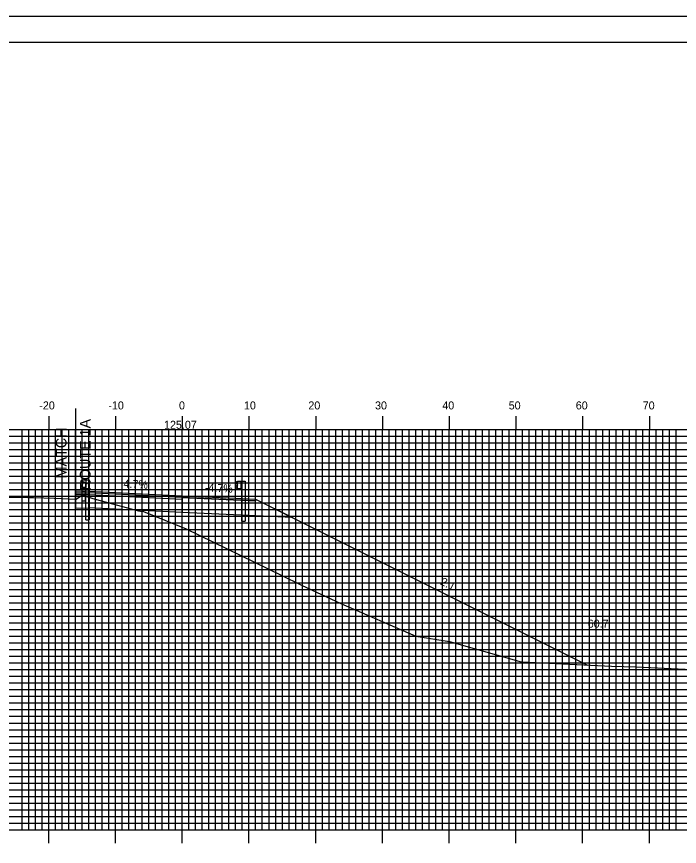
# Model space of a CAD drawing. Extents: x 857265 to 857608, y 364366 to 364586.
# Drawn here: x 857405.5 to 857504.8, y 364461.3 to 364585.7 of the extents above; entities that cross this region are included whole.
import ezdxf

# ---------------------------------------------------------------- set-up
doc = ezdxf.new("R2010")
doc.units = 0
for name, color, linetype in [('ANNOTATION', 7, 'Continuous'), ('BORDER', 7, 'Continuous'), ('D_Guardrail_Beam_Rt', 7, 'Continuous'), ('D_Roadway_Centerline_Text', 7, 'Continuous'), ('D_Roadway_Edge_Shoulder', 7, 'Continuous'), ('D_Roadway_Edge_TW', 7, 'Continuous'), ('D_Roadway_Pavement', 7, 'Continuous'), ('D_Roadway_SlopeLines', 7, 'Continuous'), ('D_Roadway_SubGrade', 7, 'Continuous'), ('D_Text_Standard', 7, 'Continuous'), ('H_V ANNOTATION', 7, 'Continuous'), ('MAJOR', 7, 'Continuous'), ('MINOR', 7, 'Continuous'), ('PLOT BOUNDARY', 7, 'Continuous'), ('S_Curb_Type_1', 7, 'Continuous'), ('S_Guardrail_Beam', 7, 'Continuous'), ('S_Roadway_Centerline', 7, 'Continuous')]:
    doc.layers.add(name, color=color, linetype=linetype)

msp = doc.modelspace()

# ---------------------------------------------------------------- linework, layer by layer
at = {"layer": 'BORDER'}
msp.add_lwpolyline([(857280.74, 364371.79), (857600.74, 364371.79), (857600.74, 364581.79), (857280.74, 364581.79)], close=True, dxfattribs=at)
at = {"layer": 'D_Guardrail_Beam_Rt'}
for p, q in [((857438.52, 364515.96), (857438.37, 364515.86)), ((857438.37, 364515.71), (857438.57, 364515.58)), ((857438.57, 364515.38), (857438.37, 364515.24)), ((857438.37, 364515.1), (857438.52, 364515)), ((857438.61, 364515.98), (857438.53, 364515.96)), ((857438.6, 364515.51), (857438.6, 364515.44)), ((857438.61, 364516.06), (857439.29, 364516.06)), ((857438.61, 364514.9), (857438.61, 364516.06)), ((857439.13, 364516.06), (857439.13, 364514.9)), ((857439.23, 364516.06), (857439.23, 364514.9)), ((857439.29, 364516.06), (857439.76, 364516.06)), ((857439.29, 364516.06), (857439.29, 364514.9)), ((857439.76, 364516.06), (857439.76, 364510.06)), ((857438.53, 364514.99), (857438.61, 364514.98)), ((857439.29, 364514.9), (857438.61, 364514.9)), ((857439.27, 364510.06), (857439.27, 364514.9)), ((857439.27, 364510.06), (857439.76, 364510.06))]:
    msp.add_line(p, q, dxfattribs=at)
for centre, major_axis, start_param, end_param in [((857438.42, 364515.79), (-0.0877, 0), 5.323254, 7.243116), ((857438.42, 364515.17), (-0.0877, 0), 5.323254, 7.243116), ((857438.54, 364515.92), (-0.0417, 0), 4.907132, 5.323254), ((857438.52, 364515.51), (0.0789, 0), 0, 0.959931), ((857438.52, 364515.44), (0.0789, 0), 5.323254, 6.283185), ((857438.54, 364515.03), (-0.0417, 0), 0.959931, 1.376053)]:
    msp.add_ellipse(centre, major_axis=major_axis, ratio=0.995501, start_param=start_param, end_param=end_param, dxfattribs=at)
at = {"layer": 'D_Roadway_Edge_Shoulder'}
msp.add_lwpolyline([(857414.34, 364514.23), (857416.34, 364514.27), (857416.34, 364514.52), (857414.34, 364514.48)], dxfattribs=at)
msp.add_lwpolyline([(857430.34, 364513.86), (857438.34, 364513.48), (857438.34, 364513.48), (857441.34, 364513.34), (857441.34, 364513.09), (857430.34, 364513.61)], close=True, dxfattribs=at)
at = {"layer": 'D_Roadway_Edge_TW'}
msp.add_lwpolyline([(857416.34, 364514.52), (857430.34, 364513.86), (857430.34, 364513.61), (857416.34, 364514.27)], close=True, dxfattribs=at)
at = {"layer": 'D_Roadway_Pavement'}
for points in [[(857414.34, 364513.98), (857416.34, 364514.02), (857416.34, 364514.27), (857414.34, 364514.23)], [(857430.34, 364513.61), (857430.34, 364513.36)], [(857430.34, 364513.61), (857430.34, 364513.36)], [(857430.34, 364513.61), (857430.34, 364513.36)], [(857430.34, 364513.61), (857430.34, 364513.36)]]:
    msp.add_lwpolyline(points, dxfattribs=at)
at = {"layer": 'D_Roadway_SlopeLines'}
msp.add_line((857441.34, 364513.34), (857491.08, 364488.48), dxfattribs=at)
at = {"layer": 'D_Roadway_SubGrade'}
msp.add_line((857414.34, 364526.92), (857414.34, 364511.96), dxfattribs=at)
msp.add_lwpolyline([(857414.34, 364511.98), (857416.34, 364512.02), (857416.34, 364514.02), (857414.34, 364513.98)], dxfattribs=at)
for points in [[(857416.34, 364514.02), (857430.34, 364513.36), (857430.34, 364511.36), (857416.34, 364512.02)], [(857430.34, 364513.36), (857430.34, 364513.61), (857441.34, 364513.09), (857441.34, 364513.34), (857446.86, 364510.57), (857430.34, 364511.36)]]:
    msp.add_lwpolyline(points, close=True, dxfattribs=at)
at = {"layer": 'MAJOR'}
for p, q in [((857410.34, 364525.79), (857410.34, 364523.79)), ((857420.34, 364525.79), (857420.34, 364523.79)), ((857430.34, 364525.79), (857430.34, 364523.79)), ((857440.34, 364525.79), (857440.34, 364523.79)), ((857450.34, 364525.79), (857450.34, 364523.79)), ((857460.34, 364525.79), (857460.34, 364523.79)), ((857470.34, 364525.79), (857470.34, 364523.79)), ((857480.34, 364525.79), (857480.34, 364523.79)), ((857490.34, 364525.79), (857490.34, 364523.79)), ((857500.34, 364525.79), (857500.34, 364523.79)), ((857290.34, 364523.79), (857570.34, 364523.79)), ((857290.34, 364523.79), (857570.34, 364523.79)), ((857410.34, 364463.79), (857410.34, 364523.79)), ((857420.34, 364463.79), (857420.34, 364523.79)), ((857430.34, 364463.79), (857430.34, 364523.79)), ((857440.34, 364463.79), (857440.34, 364523.79)), ((857450.34, 364463.79), (857450.34, 364523.79)), ((857460.34, 364463.79), (857460.34, 364523.79)), ((857470.34, 364463.79), (857470.34, 364523.79)), ((857480.34, 364463.79), (857480.34, 364523.79)), ((857490.34, 364463.79), (857490.34, 364523.79)), ((857500.34, 364463.79), (857500.34, 364523.79)), ((857290.34, 364518.79), (857570.34, 364518.79)), ((857290.34, 364513.79), (857570.34, 364513.79)), ((857290.34, 364508.79), (857570.34, 364508.79)), ((857290.34, 364503.79), (857570.34, 364503.79)), ((857290.34, 364498.79), (857570.34, 364498.79)), ((857290.34, 364493.79), (857570.34, 364493.79)), ((857290.34, 364488.79), (857570.34, 364488.79)), ((857290.34, 364483.79), (857570.34, 364483.79)), ((857290.34, 364478.79), (857570.34, 364478.79)), ((857290.34, 364473.79), (857570.34, 364473.79)), ((857290.34, 364468.79), (857570.34, 364468.79)), ((857290.34, 364463.79), (857570.34, 364463.79)), ((857290.34, 364463.79), (857570.34, 364463.79)), ((857410.34, 364461.78), (857410.34, 364463.79)), ((857420.34, 364461.78), (857420.34, 364463.79)), ((857430.34, 364461.78), (857430.34, 364463.79)), ((857440.34, 364461.78), (857440.34, 364463.79)), ((857450.34, 364461.78), (857450.34, 364463.79)), ((857460.34, 364461.78), (857460.34, 364463.79)), ((857470.34, 364461.78), (857470.34, 364463.79)), ((857480.34, 364461.78), (857480.34, 364463.79)), ((857490.34, 364461.78), (857490.34, 364463.79)), ((857500.34, 364461.78), (857500.34, 364463.79))]:
    msp.add_line(p, q, dxfattribs=at)
at = {"layer": 'MINOR'}
for p, q in [((857290.34, 364522.79), (857570.34, 364522.79)), ((857406.34, 364463.79), (857406.34, 364523.79)), ((857407.34, 364463.79), (857407.34, 364523.79)), ((857408.34, 364463.79), (857408.34, 364523.79)), ((857409.34, 364463.79), (857409.34, 364523.79)), ((857411.34, 364463.79), (857411.34, 364523.79)), ((857412.34, 364463.79), (857412.34, 364523.79)), ((857413.34, 364463.79), (857413.34, 364523.79)), ((857414.34, 364463.79), (857414.34, 364523.79)), ((857415.34, 364463.79), (857415.34, 364523.79)), ((857416.34, 364463.79), (857416.34, 364523.79)), ((857417.34, 364463.79), (857417.34, 364523.79)), ((857418.34, 364463.79), (857418.34, 364523.79)), ((857419.34, 364463.79), (857419.34, 364523.79)), ((857421.34, 364463.79), (857421.34, 364523.79)), ((857422.34, 364463.79), (857422.34, 364523.79)), ((857423.34, 364463.79), (857423.34, 364523.79)), ((857424.34, 364463.79), (857424.34, 364523.79)), ((857425.34, 364463.79), (857425.34, 364523.79)), ((857426.34, 364463.79), (857426.34, 364523.79)), ((857427.34, 364463.79), (857427.34, 364523.79)), ((857428.34, 364463.79), (857428.34, 364523.79)), ((857429.34, 364463.79), (857429.34, 364523.79)), ((857431.34, 364463.79), (857431.34, 364523.79)), ((857432.34, 364463.79), (857432.34, 364523.79)), ((857433.34, 364463.79), (857433.34, 364523.79)), ((857434.34, 364463.79), (857434.34, 364523.79)), ((857435.34, 364463.79), (857435.34, 364523.79)), ((857436.34, 364463.79), (857436.34, 364523.79)), ((857437.34, 364463.79), (857437.34, 364523.79)), ((857438.34, 364463.79), (857438.34, 364523.79)), ((857439.34, 364463.79), (857439.34, 364523.79)), ((857441.34, 364463.79), (857441.34, 364523.79)), ((857442.34, 364463.79), (857442.34, 364523.79)), ((857443.34, 364463.79), (857443.34, 364523.79)), ((857444.34, 364463.79), (857444.34, 364523.79)), ((857445.34, 364463.79), (857445.34, 364523.79)), ((857446.34, 364463.79), (857446.34, 364523.79)), ((857447.34, 364463.79), (857447.34, 364523.79)), ((857448.34, 364463.79), (857448.34, 364523.79)), ((857449.34, 364463.79), (857449.34, 364523.79)), ((857451.34, 364463.79), (857451.34, 364523.79)), ((857452.34, 364463.79), (857452.34, 364523.79)), ((857453.34, 364463.79), (857453.34, 364523.79)), ((857454.34, 364463.79), (857454.34, 364523.79)), ((857455.34, 364463.79), (857455.34, 364523.79)), ((857456.34, 364463.79), (857456.34, 364523.79)), ((857457.34, 364463.79), (857457.34, 364523.79)), ((857458.34, 364463.79), (857458.34, 364523.79)), ((857459.34, 364463.79), (857459.34, 364523.79)), ((857461.34, 364463.79), (857461.34, 364523.79)), ((857462.34, 364463.79), (857462.34, 364523.79)), ((857463.34, 364463.79), (857463.34, 364523.79)), ((857464.34, 364463.79), (857464.34, 364523.79)), ((857465.34, 364463.79), (857465.34, 364523.79)), ((857466.34, 364463.79), (857466.34, 364523.79)), ((857467.34, 364463.79), (857467.34, 364523.79)), ((857468.34, 364463.79), (857468.34, 364523.79)), ((857469.34, 364463.79), (857469.34, 364523.79)), ((857471.34, 364463.79), (857471.34, 364523.79)), ((857472.34, 364463.79), (857472.34, 364523.79)), ((857473.34, 364463.79), (857473.34, 364523.79)), ((857474.34, 364463.79), (857474.34, 364523.79)), ((857475.34, 364463.79), (857475.34, 364523.79)), ((857476.34, 364463.79), (857476.34, 364523.79)), ((857477.34, 364463.79), (857477.34, 364523.79)), ((857478.34, 364463.79), (857478.34, 364523.79)), ((857479.34, 364463.79), (857479.34, 364523.79)), ((857481.34, 364463.79), (857481.34, 364523.79)), ((857482.34, 364463.79), (857482.34, 364523.79)), ((857483.34, 364463.79), (857483.34, 364523.79)), ((857484.34, 364463.79), (857484.34, 364523.79)), ((857485.34, 364463.79), (857485.34, 364523.79)), ((857486.34, 364463.79), (857486.34, 364523.79)), ((857487.34, 364463.79), (857487.34, 364523.79)), ((857488.34, 364463.79), (857488.34, 364523.79)), ((857489.34, 364463.79), (857489.34, 364523.79)), ((857491.34, 364463.79), (857491.34, 364523.79)), ((857492.34, 364463.79), (857492.34, 364523.79)), ((857493.34, 364463.79), (857493.34, 364523.79)), ((857494.34, 364463.79), (857494.34, 364523.79)), ((857495.34, 364463.79), (857495.34, 364523.79)), ((857496.34, 364463.79), (857496.34, 364523.79)), ((857497.34, 364463.79), (857497.34, 364523.79)), ((857498.34, 364463.79), (857498.34, 364523.79)), ((857499.34, 364463.79), (857499.34, 364523.79)), ((857501.34, 364463.79), (857501.34, 364523.79)), ((857502.34, 364463.79), (857502.34, 364523.79)), ((857503.34, 364463.79), (857503.34, 364523.79)), ((857504.34, 364463.79), (857504.34, 364523.79)), ((857290.34, 364521.79), (857570.34, 364521.79)), ((857290.34, 364520.79), (857570.34, 364520.79)), ((857290.34, 364519.79), (857570.34, 364519.79)), ((857290.34, 364517.79), (857570.34, 364517.79)), ((857290.34, 364516.79), (857570.34, 364516.79)), ((857290.34, 364515.79), (857570.34, 364515.79)), ((857290.34, 364514.79), (857570.34, 364514.79)), ((857290.34, 364512.79), (857570.34, 364512.79)), ((857290.34, 364511.79), (857570.34, 364511.79)), ((857290.34, 364510.79), (857570.34, 364510.79)), ((857290.34, 364509.79), (857570.34, 364509.79)), ((857290.34, 364507.79), (857570.34, 364507.79)), ((857290.34, 364506.79), (857570.34, 364506.79)), ((857290.34, 364505.79), (857570.34, 364505.79)), ((857290.34, 364504.79), (857570.34, 364504.79)), ((857290.34, 364502.79), (857570.34, 364502.79)), ((857290.34, 364501.79), (857570.34, 364501.79)), ((857290.34, 364500.79), (857570.34, 364500.79)), ((857290.34, 364499.79), (857570.34, 364499.79)), ((857290.34, 364497.79), (857570.34, 364497.79)), ((857290.34, 364496.79), (857570.34, 364496.79)), ((857290.34, 364495.79), (857570.34, 364495.79)), ((857290.34, 364494.79), (857570.34, 364494.79)), ((857290.34, 364492.79), (857570.34, 364492.79)), ((857290.34, 364491.79), (857570.34, 364491.79)), ((857290.34, 364490.79), (857570.34, 364490.79)), ((857290.34, 364489.79), (857570.34, 364489.79)), ((857290.34, 364487.79), (857570.34, 364487.79)), ((857290.34, 364486.79), (857570.34, 364486.79)), ((857290.34, 364485.79), (857570.34, 364485.79)), ((857290.34, 364484.79), (857570.34, 364484.79)), ((857290.34, 364482.79), (857570.34, 364482.79)), ((857290.34, 364481.79), (857570.34, 364481.79)), ((857290.34, 364480.79), (857570.34, 364480.79)), ((857290.34, 364479.79), (857570.34, 364479.79)), ((857290.34, 364477.79), (857570.34, 364477.79)), ((857290.34, 364476.79), (857570.34, 364476.79)), ((857290.34, 364475.79), (857570.34, 364475.79)), ((857290.34, 364474.79), (857570.34, 364474.79)), ((857290.34, 364472.79), (857570.34, 364472.79)), ((857290.34, 364471.79), (857570.34, 364471.79)), ((857290.34, 364470.79), (857570.34, 364470.79)), ((857290.34, 364469.79), (857570.34, 364469.79)), ((857290.34, 364467.79), (857570.34, 364467.79)), ((857290.34, 364466.79), (857570.34, 364466.79)), ((857290.34, 364465.79), (857570.34, 364465.79)), ((857290.34, 364464.79), (857570.34, 364464.79))]:
    msp.add_line(p, q, dxfattribs=at)
at = {"layer": 'PLOT BOUNDARY'}
msp.add_lwpolyline([(857264.55, 364365.67), (857604.55, 364365.67), (857604.55, 364585.67), (857264.55, 364585.67)], close=True, dxfattribs=at)
at = {"layer": 'S_Curb_Type_1'}
msp.add_lwpolyline([(857415.35, 364514.53), (857415.77, 364514.53), (857415.77, 364513.03), (857415.35, 364513.03)], close=True, dxfattribs=at)
msp.add_lwpolyline([(857415.35, 364514.53), (857415.77, 364514.53), (857415.77, 364513.03), (857415.35, 364513.03)], close=True, dxfattribs=at)
at = {"layer": 'S_Guardrail_Beam'}
for p, q in [((857415.3, 364516.14), (857415.15, 364516.04)), ((857415.15, 364515.9), (857415.35, 364515.76)), ((857415.35, 364515.54), (857415.15, 364515.41)), ((857415.15, 364515.26), (857415.3, 364515.16)), ((857415.4, 364516.16), (857415.31, 364516.15)), ((857415.31, 364515.16), (857415.4, 364515.14)), ((857415.38, 364515.7), (857415.38, 364515.61)), ((857415.4, 364516.24), (857415.89, 364516.24)), ((857415.4, 364515.07), (857415.4, 364516.24)), ((857415.89, 364516.24), (857416.38, 364516.24)), ((857415.89, 364516.24), (857415.89, 364515.07)), ((857416.38, 364516.24), (857416.38, 364510.24)), ((857415.89, 364515.07), (857415.4, 364515.07)), ((857415.89, 364510.24), (857415.89, 364515.07)), ((857415.89, 364510.24), (857416.38, 364510.24))]:
    msp.add_line(p, q, dxfattribs=at)
for centre, major_axis, start_param, end_param in [((857415.2, 364515.97), (-0.0877, 0), 5.323254, 7.243116), ((857415.2, 364515.33), (-0.0877, 0), 5.323254, 7.243116), ((857415.32, 364516.11), (-0.0417, 0), 4.886922, 5.323254), ((857415.32, 364515.2), (-0.0417, 0), 0.959931, 1.396263), ((857415.3, 364515.7), (0.0789, 0), 0, 0.959931), ((857415.3, 364515.61), (0.0789, 0), 5.323254, 6.283185)]:
    msp.add_ellipse(centre, major_axis=major_axis, ratio=0.995501, start_param=start_param, end_param=end_param, dxfattribs=at)
at = {"layer": 'S_Roadway_Centerline'}
msp.add_lwpolyline([(857394.05, 364513.77), (857407.18, 364513.58), (857408.07, 364513.57), (857411.16, 364513.47), (857414.47, 364513.36), (857414.48, 364513.38), (857415.35, 364513.94), (857417.43, 364513.28), (857417.47, 364513.27), (857423.78, 364511.61), (857424.09, 364511.52), (857424.53, 364511.5), (857430.91, 364508.88), (857445.18, 364501.95), (857448.22, 364500.46), (857454.12, 364497.72), (857465.35, 364492.81), (857470.37, 364492.01), (857481.13, 364488.98), (857494.65, 364488.3), (857498.39, 364488.22), (857505.71, 364487.85)], dxfattribs=at)

# ---------------------------------------------------------------- texts
at = {"layer": 'ANNOTATION'}
for s, height, rotation, p in [('ROUTE 1A', 1.6, 90, (857416.6, 364514.66)), ('MATCH', 1.6, 90, (857413, 364516.46)), ('4.7%', 1.2, 357.2868, (857421.52, 364515.08)), ('-4.7%', 1.2, 357.2868, (857433.7, 364514.5)), ('2:1', 1.2, 333.4349, (857468.9, 364500.61))]:
    msp.add_text(s, height=height, rotation=rotation, dxfattribs=at).set_placement(p)
at = {"layer": 'D_Roadway_Centerline_Text'}
msp.add_text('125.07', height=1.2, dxfattribs=at).set_placement((857427.61, 364523.89))
at = {"layer": 'D_Text_Standard'}
msp.add_text("60.7'", height=1.2, dxfattribs=at).set_placement((857491.1, 364494.08))
at = {"layer": 'H_V ANNOTATION'}
for s, p in [('-20', (857408.92, 364526.79)), ('-10', (857419.27, 364526.79)), ('0', (857429.85, 364526.79)), ('10', (857439.59, 364526.79)), ('20', (857449.24, 364526.79)), ('30', (857459.23, 364526.79)), ('40', (857469.31, 364526.79)), ('50', (857479.26, 364526.79)), ('60', (857489.31, 364526.79)), ('70', (857499.34, 364526.79))]:
    msp.add_text(s, height=1.2, dxfattribs=at).set_placement(p)

doc.saveas('drawing.dxf')
